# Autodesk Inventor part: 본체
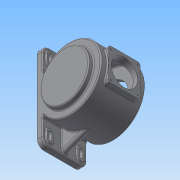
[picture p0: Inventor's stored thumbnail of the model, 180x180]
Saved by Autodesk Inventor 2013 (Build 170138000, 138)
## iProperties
Created: 2015-06
Part Number: 본체
Material: 일반
Document SubType Name: Modeling
Designer: ST4
Density: 1 g/cm^3
Author: ST4
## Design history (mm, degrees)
sketch "스케치1"
  geometry: C1 r 85 at (0, 0); 1 further point
  constraints: 1 centre point, 1 coincident
  dimensions: "d0" = 170 diameter of C1
extrude "돌출1" new body sketch "스케치1" stored distance "d2" = 118; taper "d3" = 0 deg
node "작업 평면2"
sketch "스케치9"
  geometry: L1 (-115, 59)-(115, 59); L2 (115, 59)-(115, -59); L3 (115, -59)-(-115, -59); L4 (-115, -59)-(-115, 59); 3 further points
  constraints: 8 end point, 2 midpoint, 2 parallel, 1 horizontal, 1 horizontal alignment, 1 perpendicular, 1 vertical alignment
  dimensions: "d38" = 230 distance of L1.start L1.end; "d40" = 118 distance of L3.end L1.start
extrude "돌출8" join sketch "스케치9" distance "d41" = 14; taper "d42" = 0 deg
sketch "스케치2"
  geometry: C1 r 85 at (0, 0) reference; C2 r 65 at (0, 0)
  constraints: 1 centre point, 1 coincident
  dimensions: "d4" = 130 diameter of C2
extrude "돌출2" join sketch "스케치2" distance "d6" = 13; taper "d7" = 0 deg
sketch "스케치3"
  geometry: C1 r 85 at (0, 0) reference; C2 r 65 at (0, 0)
  constraints: 1 centre point, 1 coincident
  dimensions: "d8" = 130 diameter of C2
extrude "돌출3" join sketch "스케치3" distance "d10" = 3; taper "d11" = 0 deg
sketch "스케치4"
  geometry: L1 (-85, -59)-(-85, 59) reference; L2 (-65, -62)-(65, -62) reference; L3 (65, 72)-(-65, 72) reference; L4 (0, 72)-(0, -62); L5 (0, 64.5)-(15, 64.5); L6 (15, 64.5)-(15, 61.5); L7 (15, 61.5)-(23.5, 61.5); L8 (23.5, 61.5)-(23.5, 47.5); L9 (23.5, 47.5)-(31, 47.5); L10 (31, 47.5)-(32.632, 51); L11 (32.632, 51)-(77, 51); L12 (77, 51)-(77, -51); L13 (77, -51)-(47.5, -51); L14 (85, 59)-(-85, 59) reference; L15 (47.5, -51)-(47.5, -62); 1 further point
  constraints: 22 end point, 5 parallel, 5 perpendicular, 3 point on line, 2 midpoint
  dimensions: "d12" = 154 diameter of L12 L4; "d14" = 30 diameter of L6 L4; "d15" = 47 diameter of L8 L4; "d16" = 115 deg angle of L10 L11; "d17" = 62 diameter of L9.end L4; "d18" = 3.5 distance between parallel lines of L9 L11; "d19" = 102 distance between parallel lines of L13 L11; "d20" = 3 distance between parallel lines of L7 L5; "d21" = 14 distance of L7.end L8.end; "d22" = 8 distance between parallel lines of L11 L14; "d23" = 95 diameter of L15 L4
revolve "회전1" sketch "스케치4" stored, may be unused: angle "d24" = 90 deg
node "작업 평면1"
sketch "스케치5"
  geometry: L1 (-42.5, 42.5)-(42.5, 42.5); L2 (42.5, 42.5)-(42.5, -42.5); L3 (42.5, -42.5)-(-42.5, -42.5); L4 (-42.5, -42.5)-(-42.5, 42.5); 3 further points
  constraints: 8 end point, 2 midpoint, 2 parallel, 1 horizontal, 1 horizontal alignment, 1 perpendicular, 1 vertical alignment
  dimensions: "d25" = 85 distance of L1.start L1.end; "d27" = 85 distance of L1.end L2.end
extrude "돌출4" join sketch "스케치5" distance "d28" = 3; taper "d29" = 0 deg
sketch "스케치6"
  geometry: L1 (42.5, 0)-(-42.5, 0) reference; L2 (42.5, 0)-(42.5, 42.5) reference; L3 (42.5, 42.5)-(-42.5, 42.5) reference; L4 (-42.5, 42.5)-(-42.5, 0) reference; 1 further point
extrude "돌출5" join sketch "스케치6" stored distance "d30" = 3; taper "d31" = 0 deg
sketch "스케치7"
  geometry: L1 (42.5, 0)-(-42.5, 0) reference; L2 (-42.5, 0)-(-42.5, -42.5) reference; L3 (-42.5, -42.5)-(42.5, -42.5) reference; L4 (42.5, -42.5)-(42.5, 0) reference; 1 further point
extrude "돌출6" join sketch "스케치7" stored distance "d32" = 3; taper "d33" = 0 deg
sketch "스케치8"
  geometry: C1 r 35 at (0, 0); 1 further point
  constraints: 1 centre point, 1 coincident
  dimensions: "d34" = 70 diameter of C1
extrude "돌출7" cut sketch "스케치8" stored distance "d36" = 3; taper "d37" = 0 deg
sketch "스케치10"
  geometry: L1 (32, -81)-(50, -81); L2 (50, -81)-(50, -97); L3 (50, -97)-(32, -97); L4 (32, -97)-(32, -81); A1 r 9 centre (41, -81) between (50, -81) and (32, -81); A2 r 9 centre (41, -97) between (32, -97) and (50, -97); 1 further point
  constraints: 8 end point, 4 point on circle, 2 centre point, 2 parallel, 2 tangent, 1 equal radius, 1 horizontal, 1 perpendicular
  dimensions: "d43" = 18 distance of L1.start L1.end; "d45" = 16 distance of L1.end L2.end; "d46" = 97 distance from line of L3 point (0, 0); "d97" = 41 horizontal distance of point (0, 0) A2.centre
extrude "돌출9" join sketch "스케치10" distance "d48" = 3; taper "d49" = 0 deg
sketch "스케치11"
  geometry: L1 (32, -81)-(32, -97) reference; L2 (50, -97)-(50, -81) reference; L3 (45, -81)-(45, -97); L4 (37, -97)-(37, -81); A1 r 9 centre (41, -81) between (50, -81) and (32, -81) reference; A2 r 9 centre (41, -97) between (32, -97) and (50, -97) reference; A3 r 4 centre (41, -81) between (45, -81) and (37, -81); A4 r 4 centre (41, -97) between (37, -97) and (45, -97); 1 further point
  constraints: 4 end point, 4 point on circle, 2 centre point, 3 other
  dimensions: "d50" = 8 distance between parallel lines of L3 L4
extrude "돌출10" cut sketch "스케치11" stored distance "d52" = 3; taper "d53" = 0 deg
sketch "스케치12"
  geometry: L1 (71, -46.733)-(71, -115) reference; L2 (4.703, -84.87)-(71, -109); A1 r 85 centre (0, 0) between (71, 46.733) and (71, -46.733) reference; 1 further point
  constraints: 2 end point, 1 point on circle, 1 point on line
  dimensions: "d54" = 110 deg angle of L1 L2; "d55" = 6 distance of L1.end L2.end
extrude "돌출11" join sketch "스케치12" stored distance "d56" = 15; taper "d57" = 0 deg
sketch "스케치13"
  geometry: C1 r 47.5 at (0, 0) reference; 1 further point
  constraints: 1 horizontal alignment
  dimensions: "d58" = 55 distance of C1.centre point (-55, 0)
hole "구멍1" sketch "스케치13" at (-55, 0) diameter "d59" = 3.242; stored, may be unused: countersink angle "d63" = 90 deg, drill point angle "d65" = 118 deg; dims "d60" = 6, "d61" = 4, "d62" = 2, "d64" = 12
sketch "스케치14"
  geometry: C1 r 35 at (0, 0) reference; 1 further point
  dimensions: "d69" = 35.5 horizontal distance of C1.centre point (-35.5, 35.5); "d70" = 35.5 horizontal distance of C1.centre point (-35.5, 35.5)
hole "구멍2" sketch "스케치14" at (-35.5, 35.5) diameter "d71" = 3.242; stored, may be unused: countersink angle "d75" = 90 deg, drill point angle "d77" = 118 deg; dims "d72" = 10, "d73" = 4, "d74" = 2, "d76" = 13
sketch "스케치15"
  geometry: L1 (-71, 115)-(-71, 46.733) reference; L2 (-85, 115)-(-71, 115) reference; L3 (-85, 115)-(-85, -115) reference; L4 (-85, -115)-(-71, -115) reference; L5 (-71, -46.733)-(-71, -115) reference; L6 (0, 0)-(35.923, -77.036); L7 (0, 0)-(0, -85); L8 (99.057, -47.596)-(-41.047, -112.928); C1 r 65 at (0, 0) reference; A1 r 85 centre (0, 0) between (-71, -46.733) and (-71, 46.733) reference
  constraints: 6 end point, 2 point on circle, 1 parallel, 1 point on line
  dimensions: "d78" = 25 deg angle of L7 L6; "d79" = 90 deg angle of L8 L6
sketch "스케치16"
  geometry: L1 (71, -115)-(71, -46.733) reference; L2 (85, -115)-(71, -115) reference; L3 (85, -115)-(85, 115) reference; L4 (85, 115)-(71, 115) reference; L5 (71, 46.733)-(71, 115) reference; L6 (-99.057, -47.596)-(41.047, -112.928) reference; C1 r 65 at (0, 0) reference; A1 r 85 centre (0, 0) between (71, 46.733) and (71, -46.733) reference; 1 further point
  constraints: 1 point on circle, 1 point on line
node "작업 평면3"
sketch "스케치17"
  geometry: 2 further points
  constraints: 2 coincident, 1 other
feature "엠보싱1" sketch "스케치17" dims "d80" = 0.5, "d81" = 0
fillet "모깎기1" dims "d82" = 7
fillet "모깎기2" dims "d83" = 18
fillet "모깎기3" dims "d84" = 3
fillet "모깎기4" dims "d85" = 7.5
fillet "모깎기5" dims "d86" = 3
fillet "모깎기6" dims "d87" = 3
fillet "모깎기7" dims "d88" = 3
fillet "모깎기8" dims "d89" = 3
fillet "모깎기9" dims "d90" = 0.3
chamfer "모따기1" distance "d91" = 1; stored, may be unused: second distance "d92" = 2, angle "d93" = 45 deg
fillet "모깎기10" dims "d94" = 0.3
fillet "모깎기11" dims "d95" = 3
fillet "모깎기12" dims "d96" = 2.9
node "솔리드1"
mirror "대칭1"
mirror "대칭2"
mirror "대칭3"
pattern_circular "원형 패턴1" dims angle "d67" = 360 deg
mirror "대칭4"
mirror "대칭5"
